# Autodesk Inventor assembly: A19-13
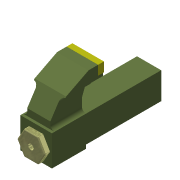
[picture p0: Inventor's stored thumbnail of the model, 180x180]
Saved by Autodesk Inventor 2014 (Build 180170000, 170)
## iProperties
Created: 2008-07
Part Number: A19-13
Document SubType Name: Assembly
Designer: y-shimohigashi
Stock Number: A19-13
Author: y-shimohigashi
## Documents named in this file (5)
- \\SVFL01\Data\技術\CAD\Inventor\テキスト\Inventor_教育Text\R2014（仮）\Inventor2014基礎コース\練習問題-19\A19-13.iam
- \\SVFL01\Data\技術\CAD\Inventor\テキスト\Inventor_教育Text\R2014（仮）\Inventor2014基礎コース\練習問題-19\P19-4締付板.ipt
- \\SVFL01\Data\技術\CAD\Inventor\テキスト\Inventor_教育Text\R2014（仮）\Inventor2014基礎コース\練習問題-19\P19-6締付ネジ押え板.ipt
- \\SVFL01\Data\技術\CAD\Inventor\テキスト\Inventor_教育Text\R2014（仮）\Inventor2014基礎コース\練習問題-19\P19-3締付金具.ipt
- \\SVFL01\Data\技術\CAD\Inventor\テキスト\Inventor_教育Text\R2014（仮）\Inventor2014基礎コース\練習問題-19\P19-11ボルト.ipt
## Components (5 placed, 4 different names)
1. P19-4締付板:1 — 挿入:3, 挿入:4
2. P19-6締付ネジ押え板:1
3. P19-3締付金具:1
4. P19-11ボルト:1 — 挿入:4
5. P19-11ボルト:2 — 挿入:3
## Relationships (2: Insert 2)
- 挿入:3 [Insert]: P19-4締付板:1 ↔ P19-11ボルト:2
- 挿入:4 [Insert]: P19-4締付板:1 ↔ P19-11ボルト:1
